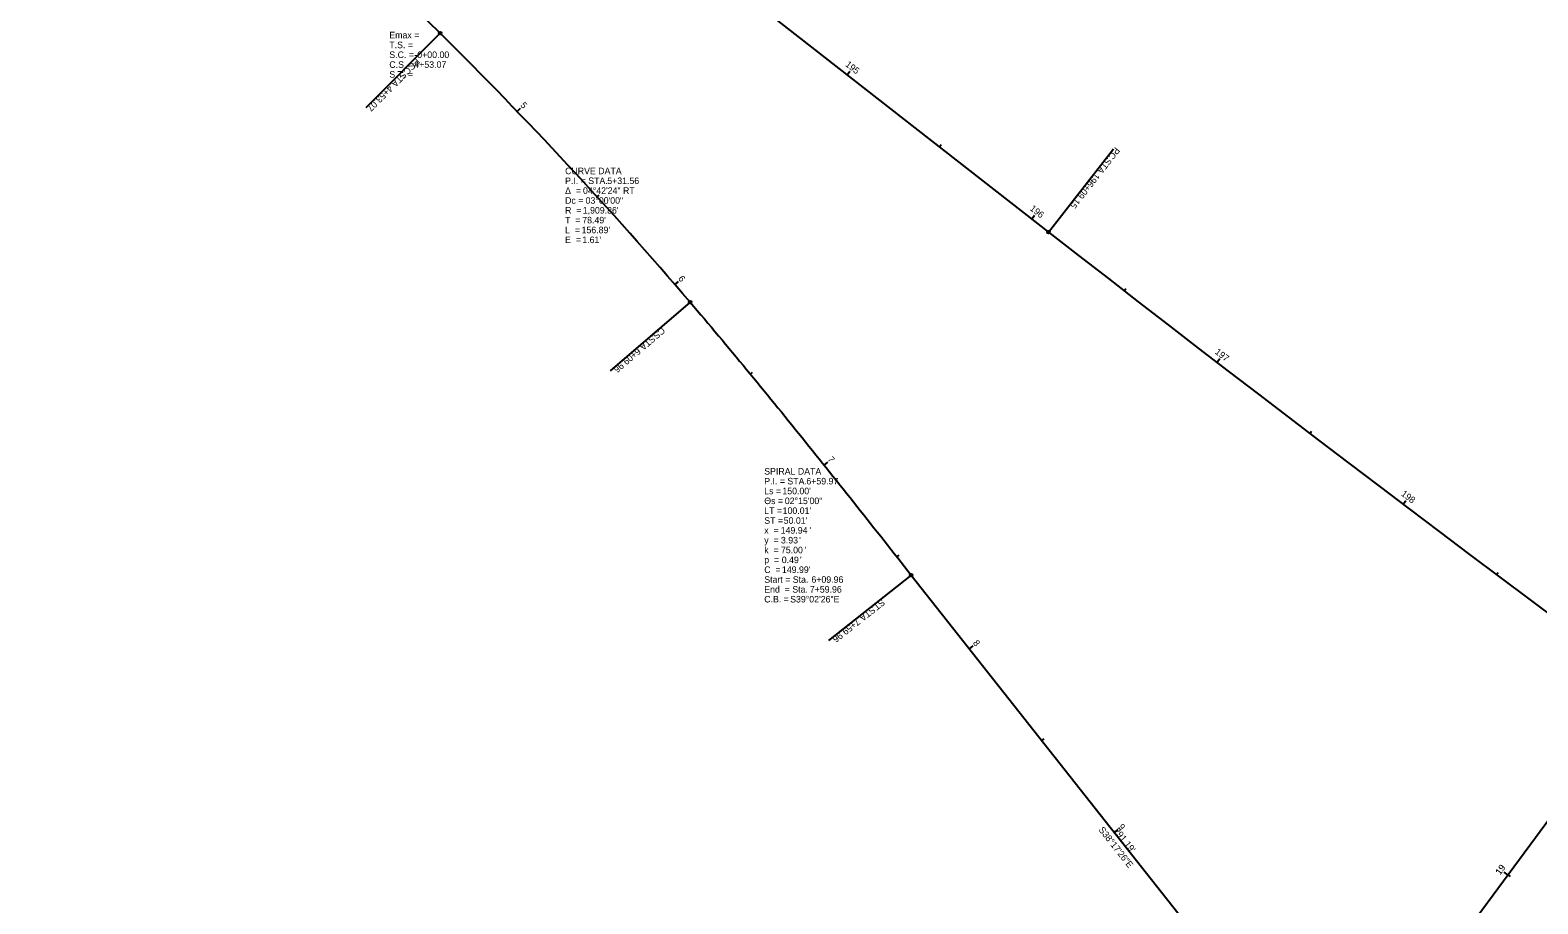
# Model space of a CAD drawing. Extents: x 1323137 to 1326838, y 458936 to 461644.
# Drawn here: x 1324445 to 1325088, y 459962 to 460335 of the extents above; entities that cross this region are included whole.
import ezdxf

# ---------------------------------------------------------------- set-up
doc = ezdxf.new("R2010")
doc.units = 0
for name, color, linetype in [('_CIVIL_CONSTRUCTION', 7, 'Continuous'), ('CM_Corridor_Final', 7, 'Continuous'), ('CM_Corridor_Range_Final', 7, 'Continuous'), ('Default', 7, 'Continuous'), ('DR_P_Ditch', 7, 'Continuous'), ('MD_P_Surface_Asphalt_Concrete_Intermediate_Course', 7, 'Continuous'), ('PV_P_Shoulder', 7, 'Continuous'), ('RD_P_GR_Rt', 7, 'Continuous'), ('SG_P_Conduit', 7, 'Continuous'), ('SG_P_Mast_Arm', 7, 'Continuous'), ('SG_P_Wiring', 7, 'Continuous'), ('SN_P_Signs', 7, 'Continuous'), ('SN_X_Public', 7, 'Continuous'), ('UT_P_Electric_Cells', 7, 'Continuous'), ('UT_X_Electric_Cells', 7, 'Continuous')]:
    doc.layers.add(name, color=color, linetype=linetype)

msp = doc.modelspace()

# ---------------------------------------------------------------- linework, layer by layer
at = {"layer": '_CIVIL_CONSTRUCTION'}
for p, q in [((1324619.64, 460333.38), (1324587.96, 460301.43)), ((1324879.49, 460248.43), (1324907.17, 460283.91)), ((1324726.4, 460218.48), (1324692.2, 460189.23)), ((1324820.87, 460101.98), (1324785.55, 460074.09))]:
    msp.add_line(p, q, dxfattribs=at)
for centre in [(1324619.64, 460333.38), (1324879.49, 460248.43), (1324726.4, 460218.48), (1324820.87, 460101.98)]:
    msp.add_circle(centre, 0.6, dxfattribs=at)
at = {"layer": 'CM_Corridor_Range_Final'}
for p, q in [((1324793.43, 460315.56), (1324794.66, 460317.14)), ((1324652.56, 460299.94), (1324654, 460301.32)), ((1324832.85, 460284.81), (1324833.59, 460285.76)), ((1324686.71, 460263.43), (1324687.6, 460264.23)), ((1324872.28, 460254.06), (1324873.51, 460255.63)), ((1324719.9, 460226.03), (1324721.41, 460227.34)), ((1324911.74, 460223.36), (1324912.48, 460224.3)), ((1324951.33, 460192.81), (1324952.55, 460194.4)), ((1324752.13, 460187.8), (1324753.05, 460188.57)), ((1324991.04, 460162.44), (1324991.77, 460163.39)), ((1324783.62, 460148.96), (1324785.18, 460150.21)), ((1325030.88, 460132.22), (1325032.08, 460133.81)), ((1324814.7, 460109.8), (1324815.64, 460110.54)), ((1325070.84, 460102.16), (1325071.55, 460103.12)), ((1324845.68, 460070.55), (1324847.25, 460071.79)), ((1324876.66, 460031.31), (1324877.6, 460032.05)), ((1324907.64, 459992.07), (1324909.21, 459993.31)), ((1325075.6, 459973.98), (1325073.99, 459975.17))]:
    msp.add_line(p, q, dxfattribs=at)
at = {"layer": 'Default'}
for p, q in [((1323137.63, 461607.2), (1324879.49, 460248.43)), ((1324820.87, 460101.98), (1325001.3, 459873.43))]:
    msp.add_line(p, q, dxfattribs=at)
for centre, radius, start, end in [((1323275.01, 458977.09), 1909.86, 40.54053, 45.2472), ((1332431.06, 469929.07), 12277.67, 232.043309, 236.873031)]:
    msp.add_arc(centre, radius, start, end, dxfattribs=at)
msp.add_open_spline([(1324726.4, 460218.48), (1324734.52, 460208.98), (1324750.6, 460189.83), (1324774.24, 460160.72), (1324797.65, 460131.43), (1324813.13, 460111.79), (1324820.87, 460101.98)], degree=3, dxfattribs=at)
at = {"layer": 'MD_P_Surface_Asphalt_Concrete_Intermediate_Course'}
for p, q in [((1324619.64, 460333.38), (1324587.96, 460301.43)), ((1324879.49, 460248.43), (1324907.17, 460283.91)), ((1324726.4, 460218.48), (1324692.2, 460189.23)), ((1324820.87, 460101.98), (1324785.55, 460074.09))]:
    msp.add_line(p, q, dxfattribs=at)
for centre in [(1324619.64, 460333.38), (1324879.49, 460248.43), (1324726.4, 460218.48), (1324820.87, 460101.98)]:
    msp.add_circle(centre, 0.6, dxfattribs=at)
at = {"layer": 'PV_P_Shoulder'}
msp.add_line((1325075.6, 459973.98), (1325076.56, 459973.27), dxfattribs=at)
at = {"layer": 'SG_P_Conduit'}
msp.add_line((1324897.32, 459732.7), (1325580.71, 460657.62), dxfattribs=at)
at = {"layer": 'SG_P_Mast_Arm'}
msp.add_line((1325075.6, 459973.98), (1325073.99, 459975.17), dxfattribs=at)
at = {"layer": 'SN_P_Signs'}
for p, q in [((1323137.63, 461607.2), (1324879.49, 460248.43)), ((1324897.32, 459732.7), (1325551, 460617.41)), ((1324820.87, 460101.98), (1325001.3, 459873.43))]:
    msp.add_line(p, q, dxfattribs=at)
for centre, radius, start, end in [((1321930.37, 457620.81), 3819.72, 45.2472, 52.04331), ((1323275.01, 458977.09), 1909.86, 40.54053, 45.2472), ((1332431.06, 469929.07), 12277.67, 232.043309, 236.873031)]:
    msp.add_arc(centre, radius, start, end, dxfattribs=at)
msp.add_open_spline([(1324726.4, 460218.48), (1324734.52, 460208.98), (1324750.6, 460189.83), (1324774.24, 460160.72), (1324797.65, 460131.43), (1324813.13, 460111.79), (1324820.87, 460101.98)], degree=3, dxfattribs=at)
at = {"layer": 'SN_X_Public'}
for p, q in [((1324793.43, 460315.56), (1324794.66, 460317.14)), ((1324652.56, 460299.94), (1324654, 460301.32)), ((1324872.28, 460254.06), (1324873.01, 460255)), ((1324719.9, 460226.03), (1324720.81, 460226.82)), ((1324951.33, 460192.81), (1324952.06, 460193.77)), ((1324783.62, 460148.96), (1324784.55, 460149.71)), ((1325030.88, 460132.22), (1325031.6, 460133.17)), ((1324845.68, 460070.55), (1324846.62, 460071.3)), ((1324907.64, 459992.07), (1324908.59, 459992.81)), ((1325075.6, 459973.98), (1325074.63, 459974.7))]:
    msp.add_line(p, q, dxfattribs=at)

# ---------------------------------------------------------------- texts
at = {"layer": '_CIVIL_CONSTRUCTION'}
for s, rotation, p in [('PCC', 225.2472, (1324609.29, 460322.89)), (' STA. ', 225.2472, (1324604.39, 460317.94)), ('4+53.07', 225.2472, (1324597.82, 460311.32)), ('PC', 232.04331, (1324907.98, 460284.89)), (' STA. ', 232.04331, (1324905.15, 460281.27)), ('196+09.15', 232.04331, (1324899.42, 460273.92)), ('CS', 220.54053, (1324714.24, 460208.03)), (' STA. ', 220.54053, (1324710.92, 460205.19)), ('6+09.96', 220.54053, (1324703.84, 460199.13)), ('ST', 218.29053, (1324808.21, 460091.94)), (' STA. ', 218.29053, (1324804.99, 460089.39)), ('7+59.96', 218.29053, (1324797.67, 460083.62))]:
    msp.add_text(s, height=2.8, rotation=rotation, dxfattribs=at).set_placement(p)
at = {"layer": 'CM_Corridor_Final'}
for s, p in [('T.S. = ', (1324597.95, 460326.95)), ('Emax = ', (1324597.95, 460331.15)), ('S.C. = ', (1324597.95, 460322.75)), ('-0+00.00', (1324608.65, 460322.75)), ('S.T. = ', (1324597.95, 460314.35)), ('C.S. = ', (1324597.95, 460318.55)), ('4+53.07', (1324608.65, 460318.55)), ('CURVE DATA', (1324673.02, 460273.13)), ('P.I. = STA. ', (1324673.02, 460268.93)), ('5+31.56', (1324691.01, 460268.93)), ('Δ  = ', (1324673.02, 460264.73)), ('04°42\'24" RT', (1324680.66, 460264.73)), ('Dc = ', (1324673.02, 460260.53)), ('R  = ', (1324673.02, 460256.33)), ("1,909.86'", (1324680.55, 460256.33)), ('03°00\'00"', (1324681.76, 460260.53)), ('T  = ', (1324673.02, 460252.13)), ("78.49'", (1324680.34, 460252.13)), ('L  = ', (1324673.02, 460247.93)), ('E  = ', (1324673.02, 460243.73)), ("156.89'", (1324680.05, 460247.93)), ("1.61'", (1324680.36, 460243.73)), ('SPIRAL DATA', (1324758.06, 460144.88)), ('P.I. = STA. ', (1324758.06, 460140.68)), ('6+59.97', (1324776.05, 460140.68)), ('Θs = ', (1324758.06, 460132.28)), ('Ls = ', (1324758.06, 460136.48)), ("150.00'", (1324765.8, 460136.48)), ('02°15\'00"', (1324766.84, 460132.28)), ('LT = ', (1324758.06, 460128.08)), ("100.01'", (1324765.91, 460128.08)), ('ST = ', (1324758.06, 460123.88)), ('149.94', (1324765.09, 460119.68)), ("50.01'", (1324766.36, 460123.88)), ("'", (1324777.34, 460119.68)), ('y  = ', (1324758.06, 460115.48)), ('x  = ', (1324758.06, 460119.68)), ('3.93', (1324765.19, 460115.48)), ("'", (1324772.97, 460115.48)), ('p  = ', (1324758.06, 460107.08)), ('k  = ', (1324758.06, 460111.28)), ('75.00', (1324765.19, 460111.28)), ('0.49', (1324765.54, 460107.08)), ("'", (1324773.32, 460107.08)), ("'", (1324775.21, 460111.28)), ('C  = ', (1324758.06, 460102.88)), ("149.99'", (1324765.61, 460102.88)), ('Start = Sta. ', (1324758.06, 460098.68)), ('End  = Sta. ', (1324758.06, 460094.48)), ('7+59.96', (1324777.52, 460094.48)), ('6+09.96', (1324778.21, 460098.68)), ('C.B. = ', (1324758.06, 460090.28)), ('S39°02\'26"E', (1324769.13, 460090.28))]:
    msp.add_text(s, height=2.8, dxfattribs=at).set_placement(p)
at = {"layer": 'CM_Corridor_Range_Final'}
for s, rotation, p in [('195', 322.04331, (1324792.44, 460319.51)), ('5', 313.83942, (1324653.69, 460302.37)), ('196', 322.04331, (1324871.25, 460258.03)), ('6', 310.83943, (1324721.13, 460228.44)), ('197', 322.46728, (1324950.28, 460196.77)), ('7', 308.65009, (1324784.94, 460151.31)), ('198', 322.93394, (1325029.79, 460136.17)), ('8', 308.29053, (1324847.01, 460072.9)), ('9', 308.29053, (1324908.99, 459994.39)), ('19', 53.54061, (1325072.33, 459973.77))]:
    msp.add_text(s, height=2.8, rotation=rotation, dxfattribs=at).set_placement(p)
at = {"layer": 'DR_P_Ditch'}
msp.add_text("291.19'", height=2.8, rotation=308.29053, dxfattribs=at).set_placement((1324907.13, 459992.78))
at = {"layer": 'MD_P_Surface_Asphalt_Concrete_Intermediate_Course'}
for s, rotation, p in [('PCC', 225.2472, (1324609.29, 460322.89)), (' STA. ', 225.2472, (1324604.39, 460317.94)), ('4+53.07', 225.2472, (1324597.82, 460311.32)), ('PC', 232.04331, (1324907.98, 460284.89)), (' STA. ', 232.04331, (1324905.15, 460281.27)), ('196+09.15', 232.04331, (1324899.42, 460273.92)), ('CS', 220.54053, (1324714.24, 460208.03)), (' STA. ', 220.54053, (1324710.92, 460205.19)), ('6+09.96', 220.54053, (1324703.84, 460199.13)), ('ST', 218.29053, (1324808.21, 460091.94)), (' STA. ', 218.29053, (1324804.99, 460089.39)), ('7+59.96', 218.29053, (1324797.67, 460083.62))]:
    msp.add_text(s, height=2.8, rotation=rotation, dxfattribs=at).set_placement(p)
at = {"layer": 'RD_P_GR_Rt'}
msp.add_text('S38°17\'26"E', height=2.8, rotation=308.29053, dxfattribs=at).set_placement((1324900.68, 459993.14))
at = {"layer": 'SG_P_Mast_Arm'}
msp.add_text('19', height=2.8, rotation=53.54061, dxfattribs=at).set_placement((1325072.28, 459973.7))
at = {"layer": 'SG_P_Wiring'}
msp.add_text('S38°17\'26"E', height=2.8, rotation=308.29053, dxfattribs=at).set_placement((1324900.68, 459993.14))
at = {"layer": 'SN_X_Public'}
for s, rotation, p in [('195', 322.04331, (1324792.44, 460319.51)), ('5', 313.83942, (1324653.69, 460302.37))]:
    msp.add_text(s, height=2.8, rotation=rotation, dxfattribs=at).set_placement(p)
at = {"layer": 'UT_P_Electric_Cells'}
for s, p in [('T.S. = ', (1324597.95, 460326.95)), ('Emax = ', (1324597.95, 460331.15)), ('S.C. = ', (1324597.95, 460322.75)), ('-0+00.00', (1324608.65, 460322.75)), ('S.T. = ', (1324597.95, 460314.35)), ('C.S. = ', (1324597.95, 460318.55)), ('4+53.07', (1324608.65, 460318.55)), ('CURVE DATA', (1324673.02, 460273.13)), ('P.I. = STA. ', (1324673.02, 460268.93)), ('5+31.56', (1324691.01, 460268.93)), ('Δ  = ', (1324673.02, 460264.73)), ('04°42\'24" RT', (1324680.66, 460264.73)), ('Dc = ', (1324673.02, 460260.53)), ('R  = ', (1324673.02, 460256.33)), ("1,909.86'", (1324680.55, 460256.33)), ('03°00\'00"', (1324681.76, 460260.53)), ('T  = ', (1324673.02, 460252.13)), ("78.49'", (1324680.34, 460252.13)), ('L  = ', (1324673.02, 460247.93)), ('E  = ', (1324673.02, 460243.73)), ("156.89'", (1324680.05, 460247.93)), ("1.61'", (1324680.36, 460243.73)), ('SPIRAL DATA', (1324758.06, 460144.88)), ('P.I. = STA. ', (1324758.06, 460140.68)), ('6+59.97', (1324776.05, 460140.68)), ('Θs = ', (1324758.06, 460132.28)), ('Ls = ', (1324758.06, 460136.48)), ("150.00'", (1324765.8, 460136.48)), ('02°15\'00"', (1324766.84, 460132.28)), ('LT = ', (1324758.06, 460128.08)), ("100.01'", (1324765.91, 460128.08)), ('ST = ', (1324758.06, 460123.88)), ('149.94', (1324765.09, 460119.68)), ("50.01'", (1324766.36, 460123.88)), ("'", (1324777.34, 460119.68)), ('y  = ', (1324758.06, 460115.48)), ('x  = ', (1324758.06, 460119.68)), ('3.93', (1324765.19, 460115.48)), ("'", (1324772.97, 460115.48)), ('p  = ', (1324758.06, 460107.08)), ('k  = ', (1324758.06, 460111.28)), ('75.00', (1324765.19, 460111.28)), ('0.49', (1324765.54, 460107.08)), ("'", (1324773.32, 460107.08)), ("'", (1324775.21, 460111.28)), ('C  = ', (1324758.06, 460102.88)), ("149.99'", (1324765.61, 460102.88)), ('Start = Sta. ', (1324758.06, 460098.68)), ('End  = Sta. ', (1324758.06, 460094.48)), ('7+59.96', (1324777.52, 460094.48)), ('6+09.96', (1324778.21, 460098.68)), ('C.B. = ', (1324758.06, 460090.28)), ('S39°02\'26"E', (1324769.13, 460090.28))]:
    msp.add_text(s, height=2.8, dxfattribs=at).set_placement(p)
at = {"layer": 'UT_X_Electric_Cells'}
msp.add_text("291.19'", height=2.8, rotation=308.29053, dxfattribs=at).set_placement((1324907.13, 459992.78))

doc.saveas('drawing.dxf')
